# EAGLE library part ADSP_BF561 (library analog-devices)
ADSP_BF561 finishd by 439390897ADSP_BF561_a.pdf at 2006.06.08 Auto generated by make-symbol-device-package-bsdl.ulp Rev. 13 Source: 37918753ADSP_BF561_256_MBGA_rev0_3.bsdl
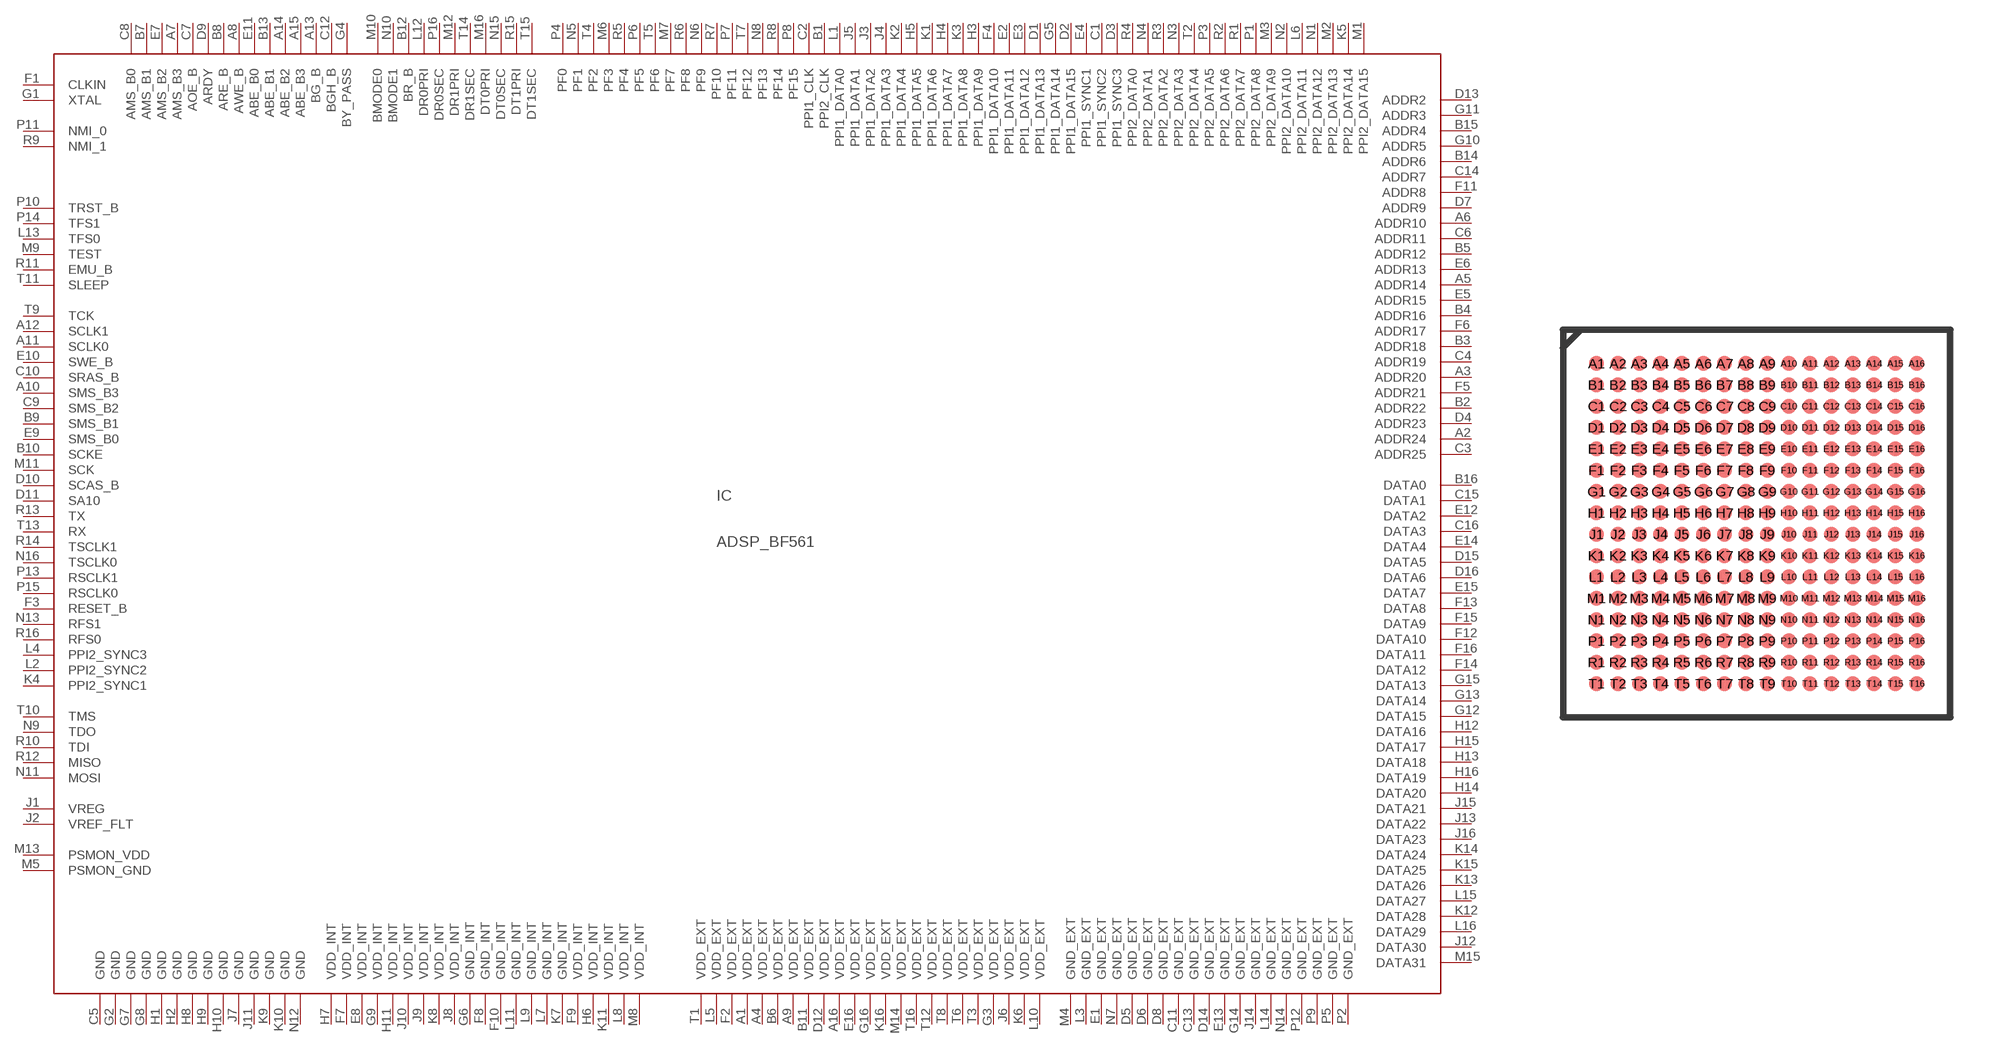
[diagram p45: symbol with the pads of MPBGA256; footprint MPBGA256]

Designator prefix IC

## ADSP_BF561-MBGA265 (OC_FARNELL: unknown; OC_NEWARK: unknown)  [MPBGA256]
A1  VDD_EXT  pwr
A2  ADDR24  out
A3  ADDR20  out
A4  VDD_EXT  pwr
A5  ADDR14  out
A6  ADDR10  out
A7  AMS_B3  out
A8  AWE_B  out
A9  VDD_EXT  pwr
A10  SMS_B3  out
A11  SCLK0  out
A12  SCLK1  out
A13  BG_B  out
A14  ABE_B2  out
A15  ABE_B3  out
A16  VDD_EXT  pwr
B1  PPI2_CLK  in
B2  ADDR22  out
B3  ADDR18  out
B4  ADDR16  out
B5  ADDR12  out
B6  VDD_EXT  pwr
B7  AMS_B1  out
B8  ARE_B  out
B9  SMS_B1  out
B10  SCKE  out
B11  VDD_EXT  pwr
B12  BR_B  in
B13  ABE_B1  out
B14  ADDR6  out
B15  ADDR4  out
B16  DATA0
C1  PPI1_SYNC2
C2  PPI1_CLK  in
C3  ADDR25  out
C4  ADDR19  out
C5  GND  pwr
C6  ADDR11  out
C7  AOE_B  out
C8  AMS_B0  out
C9  SMS_B2  out
C10  SRAS_B  out
C11  GND_EXT  pwr
C12  BGH_B  out
C13  GND_EXT  pwr
C14  ADDR7  out
C15  DATA1
C16  DATA3
D1  PPI1_DATA13
D2  PPI1_DATA15
D3  PPI1_SYNC3
D4  ADDR23  out
D5  GND_EXT  pwr
D6  GND_EXT  pwr
D7  ADDR9  out
D8  GND_EXT  pwr
D9  ARDY  in
D10  SCAS_B  out
D11  SA10  out
D12  VDD_EXT  pwr
D13  ADDR2  out
D14  GND_EXT  pwr
D15  DATA5
D16  DATA6
E1  GND_EXT  pwr
E2  PPI1_DATA11
E3  PPI1_DATA12
E4  PPI1_SYNC1
E5  ADDR15  out
E6  ADDR13  out
E7  AMS_B2  out
E8  VDD_INT  pwr
E9  SMS_B0  out
E10  SWE_B  out
E11  ABE_B0  out
E12  DATA2
E13  GND_EXT  pwr
E14  DATA4
E15  DATA7
E16  VDD_EXT  pwr
F1  CLKIN  in
F2  VDD_EXT  pwr
F3  RESET_B  in
F4  PPI1_DATA10
F5  ADDR21  out
F6  ADDR17  out
F7  VDD_INT  pwr
F8  GND_INT  pwr
F9  VDD_INT  pwr
F10  GND_INT  pwr
F11  ADDR8  out
F12  DATA10
F13  DATA8
F14  DATA12
F15  DATA9
F16  DATA11
G1  XTAL  out
G2  GND  pwr
G3  VDD_EXT  pwr
G4  BY_PASS  in
G5  PPI1_DATA14
G6  GND_INT  pwr
G7  GND  pwr
G8  GND  pwr
G9  VDD_INT  pwr
G10  ADDR5  out
G11  ADDR3  out
G12  DATA15
G13  DATA14
G14  GND_EXT  pwr
G15  DATA13
G16  VDD_EXT  pwr
H1  GND  pwr
H2  GND  pwr
H3  PPI1_DATA9
H4  PPI1_DATA7
H5  PPI1_DATA5
H6  VDD_INT  pwr
H7  VDD_INT  pwr
H8  GND  pwr
H9  GND  pwr
H10  GND  pwr
H11  VDD_INT  pwr
H12  DATA16
H13  DATA18
H14  DATA20
H15  DATA17
H16  DATA19
J1  VREG  in
J2  VREF_FLT  in
J3  PPI1_DATA2
J4  PPI1_DATA3
J5  PPI1_DATA1
J6  VDD_EXT  pwr
J7  GND  pwr
J8  VDD_INT  pwr
J9  VDD_INT  pwr
J10  VDD_INT  pwr
J11  GND  pwr
J12  DATA30
J13  DATA22
J14  GND_EXT  pwr
J15  DATA21
J16  DATA23
K1  PPI1_DATA6
K2  PPI1_DATA4
K3  PPI1_DATA8
K4  PPI2_SYNC1
K5  PPI2_DATA14
K6  VDD_EXT  pwr
K7  GND_INT  pwr
K8  VDD_INT  pwr
K9  GND  pwr
K10  GND  pwr
K11  VDD_INT  pwr
K12  DATA28
K13  DATA26
K14  DATA24
K15  DATA25
K16  VDD_EXT  pwr
L1  PPI1_DATA0
L2  PPI2_SYNC2
L3  GND_EXT  pwr
L4  PPI2_SYNC3
L5  VDD_EXT  pwr
L6  PPI2_DATA11
L7  GND_INT  pwr
L8  VDD_INT  pwr
L9  GND_INT  pwr
L10  VDD_EXT  pwr
L11  GND_INT  pwr
L12  DR0PRI
L13  TFS0
L14  GND_EXT  pwr
L15  DATA27
L16  DATA29
M1  PPI2_DATA15
M2  PPI2_DATA13
M3  PPI2_DATA9
M4  GND_EXT  pwr
M5  PSMON_GND  pwr
M6  PF3
M7  PF7
M8  VDD_INT  pwr
M9  TEST  in
M10  BMODE0  in
M11  SCK
M12  DR1PRI
M13  PSMON_VDD  pwr
M14  VDD_EXT  pwr
M15  DATA31
M16  DT0PRI
N1  PPI2_DATA12
N2  PPI2_DATA10
N3  PPI2_DATA3
N4  PPI2_DATA1
N5  PF1
N6  PF9
N7  GND_EXT  pwr
N8  PF13
N9  TDO  out
N10  BMODE1  in
N11  MOSI
N12  GND  pwr
N13  RFS1
N14  GND_EXT  pwr
N15  DT0SEC
N16  TSCLK0
P1  PPI2_DATA8
P2  GND_EXT  pwr
P3  PPI2_DATA5
P4  PF0
P5  GND_EXT  pwr
P6  PF5
P7  PF11
P8  PF15
P9  GND_EXT  pwr
P10  TRST_B  in
P11  NMI_0  in
P12  GND_EXT  pwr
P13  RSCLK1
P14  TFS1
P15  RSCLK0
P16  DR0SEC
R1  PPI2_DATA7
R2  PPI2_DATA6
R3  PPI2_DATA2
R4  PPI2_DATA0
R5  PF4
R6  PF8
R7  PF10
R8  PF14
R9  NMI_1  in
R10  TDI  in
R11  EMU_B  out
R12  MISO
R13  TX
R14  TSCLK1
R15  DT1PRI
R16  RFS0
T1  VDD_EXT  pwr
T2  PPI2_DATA4
T3  VDD_EXT  pwr
T4  PF2
T5  PF6
T6  VDD_EXT  pwr
T7  PF12
T8  VDD_EXT  pwr
T9  TCK  in
T10  TMS  in
T11  SLEEP  out
T12  VDD_EXT  pwr
T13  RX
T14  DR1SEC
T15  DT1SEC
T16  VDD_EXT  pwr

## Footprint MPBGA256 (pad centres in mm)
MBGA265 Auto generated by make-symbol-device-package-bsdl.ulp Rev. 13 Source: 37918753ADSP_BF561_256_MBGA_rev0_3.bsdl
smd 0.45 x 0.45: A1 -4.875,4.875; A2 -4.225,4.875; A3 -3.575,4.875; A4 -2.925,4.875; A5 -2.275,4.875; A6 -1.625,4.875; A7 -0.975,4.875; A8 -0.325,4.875; A9 0.325,4.875; A10 0.975,4.875; A11 1.625,4.875; A12 2.275,4.875; A13 2.925,4.875; A14 3.575,4.875; A15 4.225,4.875; A16 4.875,4.875; B1 -4.875,4.225; B2 -4.225,4.225; B3 -3.575,4.225; B4 -2.925,4.225; B5 -2.275,4.225; B6 -1.625,4.225; B7 -0.975,4.225; B8 -0.325,4.225; B9 0.325,4.225; B10 0.975,4.225; B11 1.625,4.225; B12 2.275,4.225; B13 2.925,4.225; B14 3.575,4.225; B15 4.225,4.225; B16 4.875,4.225; C1 -4.875,3.575; C2 -4.225,3.575; C3 -3.575,3.575; C4 -2.925,3.575; C5 -2.275,3.575; C6 -1.625,3.575; C7 -0.975,3.575; C8 -0.325,3.575; C9 0.325,3.575; C10 0.975,3.575; C11 1.625,3.575; C12 2.275,3.575; C13 2.925,3.575; C14 3.575,3.575; C15 4.225,3.575; C16 4.875,3.575; D1 -4.875,2.925; D2 -4.225,2.925; D3 -3.575,2.925; D4 -2.925,2.925; D5 -2.275,2.925; D6 -1.625,2.925; D7 -0.975,2.925; D8 -0.325,2.925; D9 0.325,2.925; D10 0.975,2.925; D11 1.625,2.925; D12 2.275,2.925; D13 2.925,2.925; D14 3.575,2.925; D15 4.225,2.925; D16 4.875,2.925; E1 -4.875,2.275; E2 -4.225,2.275; E3 -3.575,2.275; E4 -2.925,2.275; E5 -2.275,2.275; E6 -1.625,2.275; E7 -0.975,2.275; E8 -0.325,2.275; E9 0.325,2.275; E10 0.975,2.275; E11 1.625,2.275; E12 2.275,2.275; E13 2.925,2.275; E14 3.575,2.275; E15 4.225,2.275; E16 4.875,2.275; F1 -4.875,1.625; F2 -4.225,1.625; F3 -3.575,1.625; F4 -2.925,1.625; F5 -2.275,1.625; F6 -1.625,1.625; F7 -0.975,1.625; F8 -0.325,1.625; F9 0.325,1.625; F10 0.975,1.625; F11 1.625,1.625; F12 2.275,1.625; F13 2.925,1.625; F14 3.575,1.625; F15 4.225,1.625; F16 4.875,1.625; G1 -4.875,0.975; G2 -4.225,0.975; G3 -3.575,0.975; G4 -2.925,0.975; G5 -2.275,0.975; G6 -1.625,0.975; G7 -0.975,0.975; G8 -0.325,0.975; G9 0.325,0.975; G10 0.975,0.975; G11 1.625,0.975; G12 2.275,0.975; G13 2.925,0.975; G14 3.575,0.975; G15 4.225,0.975; G16 4.875,0.975; H1 -4.875,0.325; H2 -4.225,0.325; H3 -3.575,0.325; H4 -2.925,0.325; H5 -2.275,0.325; H6 -1.625,0.325; H7 -0.975,0.325; H8 -0.325,0.325; H9 0.325,0.325; H10 0.975,0.325; H11 1.625,0.325; H12 2.275,0.325; H13 2.925,0.325; H14 3.575,0.325; H15 4.225,0.325; H16 4.875,0.325; J1 -4.875,-0.325; J2 -4.225,-0.325; J3 -3.575,-0.325; J4 -2.925,-0.325; J5 -2.275,-0.325; J6 -1.625,-0.325; J7 -0.975,-0.325; J8 -0.325,-0.325; J9 0.325,-0.325; J10 0.975,-0.325; J11 1.625,-0.325; J12 2.275,-0.325; J13 2.925,-0.325; J14 3.575,-0.325; J15 4.225,-0.325; J16 4.875,-0.325; K1 -4.875,-0.975; K2 -4.225,-0.975; K3 -3.575,-0.975; K4 -2.925,-0.975; K5 -2.275,-0.975; K6 -1.625,-0.975; K7 -0.975,-0.975; K8 -0.325,-0.975; K9 0.325,-0.975; K10 0.975,-0.975; K11 1.625,-0.975; K12 2.275,-0.975; K13 2.925,-0.975; K14 3.575,-0.975; K15 4.225,-0.975; K16 4.875,-0.975; L1 -4.875,-1.625; L2 -4.225,-1.625; L3 -3.575,-1.625; L4 -2.925,-1.625; L5 -2.275,-1.625; L6 -1.625,-1.625; L7 -0.975,-1.625; L8 -0.325,-1.625; L9 0.325,-1.625; L10 0.975,-1.625; L11 1.625,-1.625; L12 2.275,-1.625; L13 2.925,-1.625; L14 3.575,-1.625; L15 4.225,-1.625; L16 4.875,-1.625; M1 -4.875,-2.275; M2 -4.225,-2.275; M3 -3.575,-2.275; M4 -2.925,-2.275; M5 -2.275,-2.275; M6 -1.625,-2.275; M7 -0.975,-2.275; M8 -0.325,-2.275; M9 0.325,-2.275; M10 0.975,-2.275; M11 1.625,-2.275; M12 2.275,-2.275; M13 2.925,-2.275; M14 3.575,-2.275; M15 4.225,-2.275; M16 4.875,-2.275; N1 -4.875,-2.925; N2 -4.225,-2.925; N3 -3.575,-2.925; N4 -2.925,-2.925; N5 -2.275,-2.925; N6 -1.625,-2.925; N7 -0.975,-2.925; N8 -0.325,-2.925; N9 0.325,-2.925; N10 0.975,-2.925; N11 1.625,-2.925; N12 2.275,-2.925; N13 2.925,-2.925; N14 3.575,-2.925; N15 4.225,-2.925; N16 4.875,-2.925; P1 -4.875,-3.575; P2 -4.225,-3.575; P3 -3.575,-3.575; P4 -2.925,-3.575; P5 -2.275,-3.575; P6 -1.625,-3.575; P7 -0.975,-3.575; P8 -0.325,-3.575; P9 0.325,-3.575; P10 0.975,-3.575; P11 1.625,-3.575; P12 2.275,-3.575; P13 2.925,-3.575; P14 3.575,-3.575; P15 4.225,-3.575; P16 4.875,-3.575; R1 -4.875,-4.225; R2 -4.225,-4.225; R3 -3.575,-4.225; R4 -2.925,-4.225; R5 -2.275,-4.225; R6 -1.625,-4.225; R7 -0.975,-4.225; R8 -0.325,-4.225; R9 0.325,-4.225; R10 0.975,-4.225; R11 1.625,-4.225; R12 2.275,-4.225; R13 2.925,-4.225; R14 3.575,-4.225; R15 4.225,-4.225; R16 4.875,-4.225; T1 -4.875,-4.875; T2 -4.225,-4.875; T3 -3.575,-4.875; T4 -2.925,-4.875; T5 -2.275,-4.875; T6 -1.625,-4.875; T7 -0.975,-4.875; T8 -0.325,-4.875; T9 0.325,-4.875; T10 0.975,-4.875; T11 1.625,-4.875; T12 2.275,-4.875; T13 2.925,-4.875; T14 3.575,-4.875; T15 4.225,-4.875; T16 4.875,-4.875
